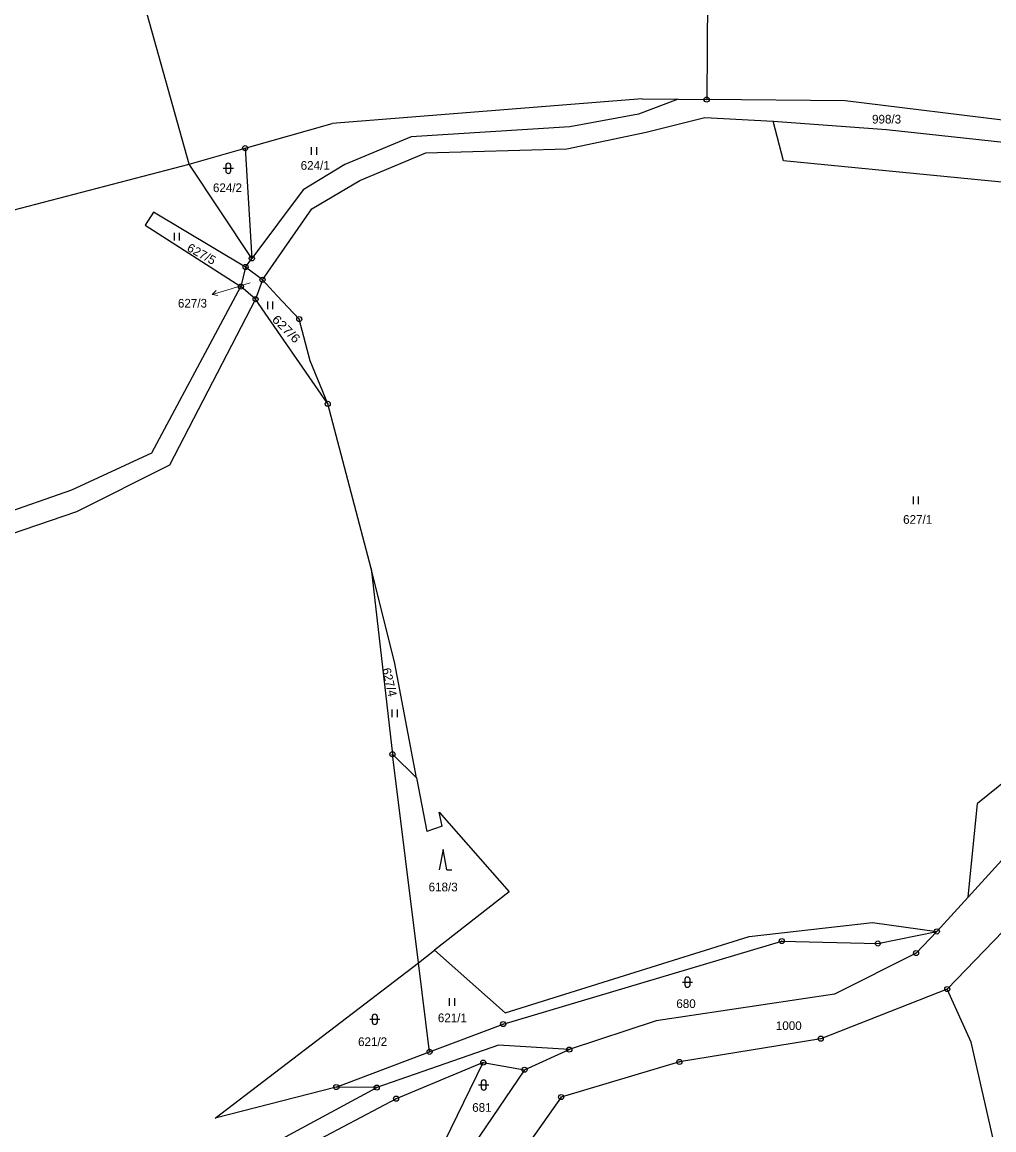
# Model space of a CAD drawing. Extents: x -754970 to -752637, y -970569 to -968179.
# Drawn here: x -754191 to -754000.8, y -969426.8 to -969210.1 of the extents above; entities that cross this region are included whole.
import ezdxf
from ezdxf.enums import TextEntityAlignment as Align

# ---------------------------------------------------------------- set-up
doc = ezdxf.new("R2010")
doc.units = 0
doc.header["$LTSCALE"] = 0.68
for name, color, linetype, lineweight in [('1', 7, 'Continuous', 25), ('3', 7, 'Continuous', 25), ('7', 7, 'Continuous', 13), ('8', 7, 'Continuous', 25)]:
    doc.layers.add(name, color=color, linetype=linetype, lineweight=lineweight)
doc.layers.add('2', color=7, linetype='Continuous')

msp = doc.modelspace()

# ---------------------------------------------------------------- linework, layer by layer
at = {"layer": '1'}
for p, q in [((-754158.25, -969237.86), (-754181, -969156.58)), ((-754056.84, -969205.22), (-754057, -969225.24)), ((-754069.65, -969225.08), (-754130.31, -969229.94)), ((-754062.6, -969225.17), (-754070.34, -969228.08)), ((-754069.65, -969225.08), (-754062.6, -969225.17)), ((-754062.6, -969225.17), (-754057, -969225.24)), ((-754029.9, -969225.5), (-754057, -969225.24)), ((-753968.11, -969233.08), (-754029.9, -969225.5)), ((-754070.34, -969228.08), (-754083.79, -969230.61)), ((-754147.33, -969234.76), (-754130.31, -969229.94)), ((-754068.84, -969231.64), (-754057.34, -969228.77)), ((-754057.34, -969228.77), (-754043.96, -969229.46)), ((-754043.96, -969229.46), (-754021.81, -969231.13)), ((-754041.96, -969237.25), (-754043.96, -969229.46)), ((-754114.84, -969232.56), (-754127.84, -969237.97)), ((-754083.79, -969230.61), (-754114.84, -969232.56)), ((-754084.37, -969234.86), (-754068.84, -969231.64)), ((-754021.81, -969231.13), (-753964.91, -969237.25)), ((-754158.25, -969237.86), (-754147.33, -969234.76)), ((-754147.33, -969234.76), (-754146.01, -969256.33)), ((-754124.85, -969241.07), (-754111.97, -969235.67)), ((-754111.97, -969235.67), (-754084.37, -969234.86)), ((-754233.28, -969257.41), (-754158.25, -969237.86)), ((-754146.01, -969256.33), (-754158.25, -969237.86)), ((-754127.84, -969237.97), (-754136, -969242.92)), ((-753989.41, -969242.38), (-754041.96, -969237.25)), ((-754134.28, -969246.6), (-754124.85, -969241.07)), ((-754136, -969242.92), (-754146.01, -969256.33)), ((-754165.28, -969247.28), (-754166.89, -969249.81)), ((-754147.24, -969258.01), (-754165.28, -969247.28)), ((-754143.93, -969260.51), (-754134.28, -969246.6)), ((-754166.89, -969249.81), (-754148.15, -969261.84)), ((-754147.24, -969258.01), (-754146.01, -969256.33)), ((-754147.24, -969258.01), (-754148.15, -969261.84)), ((-754143.93, -969260.51), (-754147.24, -969258.01)), ((-754143.93, -969260.51), (-754145.27, -969264.3)), ((-754141.07, -969263.62), (-754143.93, -969260.51)), ((-754165.61, -969294.39), (-754148.15, -969261.84)), ((-754145.27, -969264.3), (-754148.15, -969261.84)), ((-754145.27, -969264.3), (-754162.1, -969296.79)), ((-754131.16, -969284.79), (-754145.27, -969264.3)), ((-754141.07, -969263.62), (-754136.73, -969268.2)), ((-754134.61, -969276.39), (-754136.73, -969268.2)), ((-754131.16, -969284.79), (-754134.61, -969276.39)), ((-754122.68, -969317), (-754131.16, -969284.79)), ((-754181.26, -969301.58), (-754165.61, -969294.39)), ((-754162.1, -969296.79), (-754180.3, -969305.89)), ((-754210, -969311.64), (-754181.26, -969301.58)), ((-754180.3, -969305.89), (-754209.84, -969315.95)), ((-754118.01, -969335.59), (-754122.68, -969317)), ((-754122.68, -969317), (-754118.5, -969353.36)), ((-754113.78, -969357.98), (-754118.01, -969335.59)), ((-753983.16, -969346.17), (-754003.97, -969362.97)), ((-754113.78, -969357.98), (-754118.5, -969353.36)), ((-754113.4, -969394.15), (-754118.5, -969353.36)), ((-754113.78, -969357.98), (-754111.78, -969368.45)), ((-754005.83, -969381.28), (-753984.47, -969357.82)), ((-754109.33, -969364.66), (-754095.64, -969380.25)), ((-754108.77, -969367.44), (-754109.33, -969364.66)), ((-754005.83, -969381.28), (-754003.97, -969362.97)), ((-754108.77, -969367.44), (-754111.78, -969368.45)), ((-754095.64, -969380.25), (-754110.27, -969391.71)), ((-754011.96, -969388.02), (-754005.83, -969381.28)), ((-754048.71, -969389.04), (-754024.56, -969386.26)), ((-754024.56, -969386.26), (-754011.96, -969388.02)), ((-753997.17, -969386.08), (-754009.91, -969399.3)), ((-754023.5, -969390.38), (-754011.96, -969388.02)), ((-754011.96, -969388.02), (-754016.02, -969392.25)), ((-754096.82, -969406.15), (-754042.31, -969389.91)), ((-754096.45, -969403.97), (-754048.71, -969389.04)), ((-754042.31, -969389.91), (-754023.5, -969390.38)), ((-754113.4, -969394.15), (-754110.27, -969391.71)), ((-754110.27, -969391.71), (-754096.45, -969403.97)), ((-754016.02, -969392.25), (-754032, -969400.32)), ((-754153.16, -969424.56), (-754113.4, -969394.15)), ((-754111.22, -969411.58), (-754113.4, -969394.15)), ((-754009.91, -969399.3), (-754034.68, -969409)), ((-754005.25, -969409.66), (-754009.91, -969399.3)), ((-754032, -969400.32), (-754066.89, -969405.51)), ((-754066.89, -969405.51), (-754083.88, -969411.14)), ((-754111.22, -969411.58), (-754096.82, -969406.15)), ((-754097.77, -969410.29), (-754121.58, -969418.57)), ((-754083.88, -969411.14), (-754097.77, -969410.29)), ((-754034.68, -969409), (-754062.34, -969413.55)), ((-754000.93, -969428.61), (-754005.25, -969409.66)), ((-754129.48, -969418.47), (-754111.22, -969411.58)), ((-754092.65, -969415.07), (-754083.88, -969411.14)), ((-754124.36, -969461.8), (-754100.72, -969413.68)), ((-754100.72, -969413.68), (-754117.79, -969420.74)), ((-754100.72, -969413.68), (-754092.65, -969415.07)), ((-754062.34, -969413.55), (-754085.5, -969420.43)), ((-754092.65, -969415.07), (-754124.36, -969461.8)), ((-754178.72, -969449.34), (-754121.58, -969418.57)), ((-754129.48, -969418.47), (-754153.16, -969424.56)), ((-754121.58, -969418.57), (-754129.48, -969418.47)), ((-754117.79, -969420.74), (-754178.43, -969452.78)), ((-754085.5, -969420.43), (-754129.03, -969482.4))]:
    msp.add_line(p, q, dxfattribs=at)
at = {"layer": '3'}
for p, q in [((-754134.311, -969236.04), (-754134.311, -969234.54)), ((-754133.31, -969236.04), (-754133.31, -969234.54)), ((-754151.631, -969238.691), (-754149.629, -969238.691)), ((-754151.131, -969238.191), (-754151.131, -969239.192)), ((-754150.129, -969239.192), (-754150.129, -969238.191)), ((-754161.141, -969252.85), (-754161.141, -969251.35)), ((-754160.14, -969252.85), (-754160.14, -969251.35)), ((-754142.911, -969266.25), (-754142.911, -969264.75)), ((-754141.91, -969266.25), (-754141.91, -969264.75)), ((-754016.531, -969304.41), (-754016.531, -969302.91)), ((-754015.53, -969304.41), (-754015.53, -969302.91)), ((-754118.521, -969346.07), (-754118.521, -969344.57)), ((-754117.52, -969346.07), (-754117.52, -969344.57)), ((-754107.85, -969375.99), (-754106.854, -969375.99)), ((-754061.761, -969397.951), (-754059.759, -969397.951)), ((-754061.261, -969397.451), (-754061.261, -969398.452)), ((-754060.259, -969398.452), (-754060.259, -969397.451)), ((-754107.311, -969402.6), (-754107.311, -969401.1)), ((-754106.31, -969402.6), (-754106.31, -969401.1)), ((-754122.951, -969405.211), (-754120.949, -969405.211)), ((-754122.451, -969404.711), (-754122.451, -969405.712)), ((-754121.449, -969405.712), (-754121.449, -969404.711)), ((-754101.631, -969418.061), (-754099.629, -969418.061)), ((-754101.131, -969417.561), (-754101.131, -969418.562)), ((-754100.129, -969418.562), (-754100.129, -969417.561))]:
    msp.add_line(p, q, dxfattribs=at)
msp.add_lwpolyline([(-754107.85, -969375.99), (-754108.6, -969371.99), (-754109.35, -969375.99)], dxfattribs=at)
for centre, start, end in [((-754150.63, -969238.1909), 0, 180), ((-754150.63, -969239.1909), 180, 359.98789), ((-754060.76, -969397.4509), 0, 180), ((-754060.76, -969398.4509), 180, 359.98789), ((-754121.95, -969404.7109), 0, 180), ((-754121.95, -969405.7109), 180, 359.98789), ((-754100.63, -969417.5609), 0, 180), ((-754100.63, -969418.5609), 180, 359.98789)]:
    msp.add_arc(centre, 0.5, start, end, dxfattribs=at)
at = {"layer": '7'}
msp.add_line((-754153.79, -969263.387), (-754152.686, -969263.573), dxfattribs=at)
msp.add_lwpolyline([(-754146.33, -969261.09), (-754150.92, -969262.51), (-754153.79, -969263.387), (-754152.979, -969262.616)], dxfattribs=at)
at = {"layer": '8'}
for centre, radius in [((-754057, -969225.2399), 0.5), ((-754057, -969225.2399), 0.0303), ((-754147.33, -969234.7599), 0.5), ((-754147.33, -969234.7599), 0.0303), ((-754146.01, -969256.3299), 0.5), ((-754146.01, -969256.3299), 0.0303), ((-754147.24, -969258.0099), 0.5), ((-754147.24, -969258.0099), 0.0303), ((-754143.93, -969260.5099), 0.5), ((-754143.93, -969260.5099), 0.0303), ((-754148.15, -969261.8399), 0.5), ((-754148.15, -969261.8399), 0.0303), ((-754145.27, -969264.2999), 0.5), ((-754145.27, -969264.2999), 0.0303), ((-754136.73, -969268.1999), 0.5), ((-754136.73, -969268.1999), 0.0303), ((-754131.16, -969284.7899), 0.5), ((-754131.16, -969284.7899), 0.0303), ((-754118.5, -969353.3599), 0.5), ((-754118.5, -969353.3599), 0.0303), ((-754011.96, -969388.0199), 0.5), ((-754011.96, -969388.0199), 0.0303), ((-754042.31, -969389.9099), 0.5), ((-754042.31, -969389.9099), 0.0303), ((-754023.5, -969390.3799), 0.5), ((-754023.5, -969390.3799), 0.0303), ((-754016.02, -969392.2499), 0.5), ((-754016.02, -969392.2499), 0.0303), ((-754009.91, -969399.2999), 0.5), ((-754009.91, -969399.2999), 0.0303), ((-754096.82, -969406.1499), 0.5), ((-754096.82, -969406.1499), 0.0303), ((-754034.68, -969408.9999), 0.5), ((-754034.68, -969408.9999), 0.0303), ((-754111.22, -969411.5799), 0.5), ((-754111.22, -969411.5799), 0.0303), ((-754083.88, -969411.1399), 0.5), ((-754083.88, -969411.1399), 0.0303), ((-754100.72, -969413.6799), 0.5), ((-754100.72, -969413.6799), 0.0303), ((-754092.65, -969415.0699), 0.5), ((-754062.34, -969413.5499), 0.5), ((-754062.34, -969413.5499), 0.0303), ((-754092.65, -969415.0699), 0.0303), ((-754129.48, -969418.4699), 0.5), ((-754129.48, -969418.4699), 0.0303), ((-754121.58, -969418.5699), 0.5), ((-754121.58, -969418.5699), 0.0303), ((-754117.79, -969420.7399), 0.5), ((-754117.79, -969420.7399), 0.0303), ((-754085.5, -969420.4299), 0.5), ((-754085.5, -969420.4299), 0.0303)]:
    msp.add_circle(centre, radius, dxfattribs=at)

# ---------------------------------------------------------------- texts
at = {"layer": '2'}
for s, p in [('998/3', (-754021.79, -969229.935)), ('624/1', (-754133.61, -969238.985)), ('624/2', (-754150.78, -969243.355)), ('627/1', (-754015.71, -969308.255)), ('618/3', (-754108.57, -969380.175)), ('680', (-754061.039, -969402.995)), ('621/1', (-754106.76, -969405.775)), ('1000', (-754040.93, -969407.305)), ('621/2', (-754122.38, -969410.445)), ('681', (-754100.989, -969423.315))]:
    msp.add_text(s, height=1.7, dxfattribs=at).set_placement(p, align=Align.CENTER)
for s, rotation, width, p in [('627/5', 331, 1.05, (-754156.2556, -969256.1973)), ('627/6', 315, 1.15, (-754139.8835, -969270.7365))]:
    msp.add_text(s, height=1.7, rotation=rotation, dxfattribs=dict(at, width=width)).set_placement(p, align=Align.CENTER)
msp.add_text('627/3', height=1.7, dxfattribs=at).set_placement((-754154.79, -969265.955), align=Align.RIGHT)
msp.add_text('627/4', height=1.7, rotation=283, dxfattribs=at).set_placement((-754119.8915, -969339.4428), align=Align.CENTER)

doc.saveas('drawing.dxf')
